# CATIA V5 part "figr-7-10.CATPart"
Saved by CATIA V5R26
Part number: Part1
Bounding box of the stored display mesh (mm): x -75 to 75, y -50 to 50, z 0 to 50
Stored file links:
  D:\_Deepak\CATIA\CATIA V5 2015 Parts Files\Part files\Partfiles\c07_catia_v5_6r2015_prt\figr-7-10.CATPart
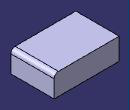
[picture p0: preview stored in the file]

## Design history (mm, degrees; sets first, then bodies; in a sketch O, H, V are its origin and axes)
Body1 (main body)
  Sketch1 on xy-plane, origin (0, 0, 0), H (1, 0, 0), V (0, 1, 0)
    line L1 (-75, 50) -> (75, 50)
    line L2 (75, 50) -> (75, -50)
    line L3 (75, -50) -> (-75, -50)
    line L4 (-75, -50) -> (-75, 50)
    axis line L5 (75, -50) -> (-75, 50)
    length L3 = 150
    length L2 = 100
    horizontal: L1 H, L3 H
    vertical: L2 V, L4 V
    midpoint: O L5
  Pad1: profile Sketch1, direction (0, 0, 1), length 50
  Fillet1: radius 10, on edge [face of Pad1 from Sketch1.L2 | end face of Pad1]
